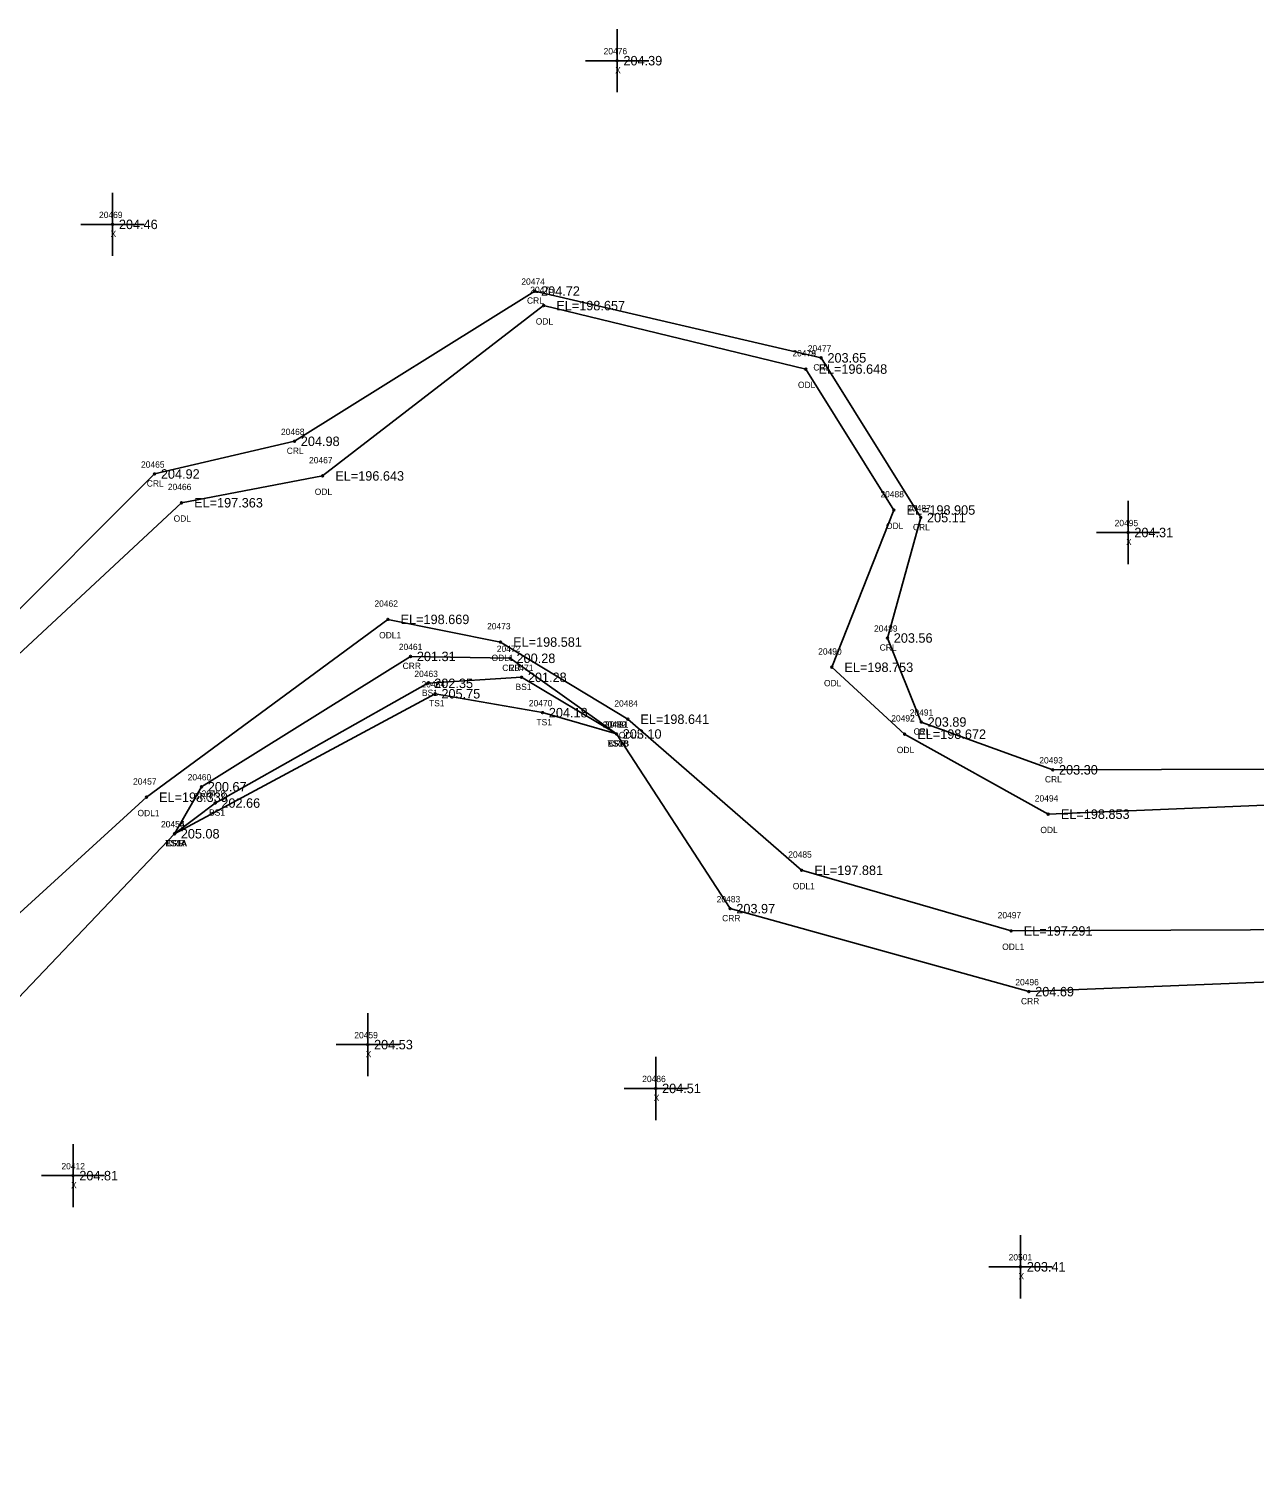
# Model space of a CAD drawing. Extents: x 2260230 to 2261304, y 1064626 to 1065587.
# Drawn here: x 2260916.2 to 2261110.1, y 1065075.6 to 1065305.6 of the extents above; entities that cross this region are included whole.
import ezdxf

# ---------------------------------------------------------------- set-up
doc = ezdxf.new("R2010")
doc.units = 0
for name, color, linetype in [('RD_DTM_BkLn2', 7, 'Continuous'), ('RD_DTM_BkLn_txCode', 7, 'Continuous'), ('RD_EX_H2O', 7, 'Continuous'), ('RD_EX_H2O_txCode', 7, 'Continuous'), ('RD_EX_Misc', 7, 'Continuous'), ('RD_EX_Misc_txCode', 7, 'Continuous'), ('RD_EX_TX_H2O_ELEV', 7, 'Continuous'), ('RD_EX_TX_Misc_ELEV', 7, 'Continuous'), ('RD_SMD_Locator', 7, 'Continuous')]:
    doc.layers.add(name, color=color, linetype=linetype)

msp = doc.modelspace()

# ---------------------------------------------------------------- linework, layer by layer
at = {"layer": 'RD_DTM_BkLn2'}
for points in [[(2260939.15, 1065178.33), (2260945.57, 1065183.19), (2260979.24, 1065202.13), (2260994.05, 1065203.08), (2261009.06, 1065194.12)], [(2260939.15, 1065178.33), (2260980.38, 1065200.48), (2260997.37, 1065197.49), (2261009.06, 1065194.12)]]:
    msp.add_lwpolyline(points, dxfattribs=at)
at = {"layer": 'RD_EX_H2O'}
for points in [[(2260885.41, 1065184.64), (2260936, 1065235.25), (2260958.14, 1065240.42), (2260996.14, 1065264.19), (2261041.44, 1065253.62), (2261057.19, 1065228.35), (2261051.93, 1065209.3), (2261057.29, 1065196.01), (2261078.07, 1065188.45), (2261181.25, 1065188.78), (2261285.07, 1065214.16)], [(2260772.5, 1065076.18), (2260808.2, 1065117.04), (2260848.54, 1065142.46), (2260881.52, 1065170.81), (2260885.55, 1065179.82), (2260940.26, 1065230.7), (2260962.59, 1065234.94), (2260997.55, 1065261.89), (2261039.02, 1065251.85), (2261039.02, 1065251.85), (2261052.94, 1065229.55), (2261043.13, 1065204.67), (2261054.65, 1065194.09), (2261077.36, 1065181.43), (2261181.44, 1065185.78), (2261286.2, 1065209.29)], [(2260798.69, 1065050.24), (2260824.47, 1065095.61), (2260899.49, 1065151.99), (2260934.71, 1065184.11), (2260972.92, 1065212.25), (2260990.72, 1065208.66), (2261010.85, 1065196.45), (2261038.36, 1065172.55), (2261071.49, 1065162.95), (2261185.1, 1065163.45), (2261291.17, 1065187.86)], [(2260835.04, 1065077.78), (2260839.45, 1065081.34), (2260836.25, 1065093.94), (2260905.11, 1065142.54), (2260939.15, 1065178.33), (2260943.42, 1065185.77), (2260976.49, 1065206.39), (2260992.26, 1065206.09), (2261009.06, 1065194.12), (2261027.03, 1065166.48), (2261074.3, 1065153.35), (2261181.18, 1065157.65), (2261291.85, 1065184.94)]]:
    msp.add_lwpolyline(points, dxfattribs=at)
at = {"layer": 'RD_EX_Misc'}
for p, q in [((2261009.17, 1065295.64), (2261009.17, 1065305.64)), ((2261004.17, 1065300.64), (2261014.17, 1065300.64)), ((2260929.36, 1065269.74), (2260929.36, 1065279.74)), ((2260924.36, 1065274.74), (2260934.36, 1065274.74)), ((2261089.99, 1065220.99), (2261089.99, 1065230.99)), ((2261084.99, 1065225.99), (2261094.99, 1065225.99)), ((2260969.72, 1065139.97), (2260969.72, 1065149.97)), ((2260964.72, 1065144.97), (2260974.72, 1065144.97)), ((2261015.28, 1065133.04), (2261015.28, 1065143.04)), ((2261010.28, 1065138.04), (2261020.28, 1065138.04)), ((2260923.1, 1065119.24), (2260923.1, 1065129.24)), ((2260918.1, 1065124.24), (2260928.1, 1065124.24)), ((2261072.97, 1065104.82), (2261072.97, 1065114.82)), ((2261067.97, 1065109.82), (2261077.97, 1065109.82))]:
    msp.add_line(p, q, dxfattribs=at)
at = {"layer": 'RD_SMD_Locator'}
for centre in [(2261009.17, 1065300.64), (2260929.36, 1065274.74), (2260996.14, 1065264.19), (2260997.55, 1065261.89), (2261041.44, 1065253.62), (2261039.02, 1065251.85), (2261039.02, 1065251.85), (2260958.14, 1065240.42), (2260936, 1065235.25), (2260962.59, 1065234.94), (2260940.26, 1065230.7), (2261052.94, 1065229.55), (2261057.19, 1065228.35), (2261089.99, 1065225.99), (2260972.92, 1065212.25), (2260990.72, 1065208.66), (2261051.93, 1065209.3), (2260976.49, 1065206.39), (2260992.26, 1065206.09), (2260994.05, 1065203.08), (2261043.13, 1065204.67), (2260979.24, 1065202.13), (2260980.38, 1065200.48), (2260997.37, 1065197.49), (2261010.85, 1065196.45), (2261057.29, 1065196.01), (2261009.06, 1065194.12), (2261009.06, 1065194.12), (2261009.06, 1065194.12), (2261054.65, 1065194.09), (2261078.07, 1065188.45), (2260934.71, 1065184.11), (2260943.42, 1065185.77), (2260945.57, 1065183.19), (2261077.36, 1065181.43), (2260939.15, 1065178.33), (2260939.15, 1065178.33), (2260939.15, 1065178.33), (2261038.36, 1065172.55), (2261027.03, 1065166.48), (2261071.49, 1065162.95), (2261074.3, 1065153.35), (2260969.72, 1065144.97), (2261015.28, 1065138.04), (2260923.1, 1065124.24), (2261072.97, 1065109.82)]:
    msp.add_circle(centre, 0.15, dxfattribs=at)

# ---------------------------------------------------------------- texts
at = {"layer": 'RD_DTM_BkLn_txCode'}
for s, p in [('20471', (2260992.21, 1065204.08)), ('20463', (2260977.1, 1065203.13)), ('20464', (2260978.23, 1065201.48)), ('BS1', (2260978.3, 1065200.13)), ('BS1', (2260993.1, 1065201.08)), ('TS1', (2260979.42, 1065198.48)), ('20470', (2260995.21, 1065198.49)), ('TS1', (2260996.41, 1065195.49)), ('20480', (2261006.91, 1065195.12)), ('20481', (2261007.23, 1065195.12)), ('TS1B', (2261007.63, 1065192.12)), ('BS1B', (2261007.65, 1065192.12)), ('20458', (2260943.45, 1065184.19)), ('BS1', (2260944.62, 1065181.19)), ('20456', (2260937.01, 1065179.33)), ('20455', (2260937.03, 1065179.33)), ('TS1A', (2260937.7, 1065176.33)), ('BS1A', (2260937.72, 1065176.33))]:
    msp.add_text(s, height=1, dxfattribs=at).set_placement(p)
at = {"layer": 'RD_EX_H2O_txCode'}
for s, p in [('20474', (2260994.02, 1065265.19)), ('20475', (2260995.43, 1065263.89)), ('CRL', (2260994.91, 1065262.19)), ('ODL', (2260996.3, 1065258.89)), ('20477', (2261039.33, 1065254.62)), ('20478', (2261036.9, 1065253.85)), ('20479', (2261036.9, 1065253.85)), ('CRL', (2261040.21, 1065251.62)), ('ODL', (2261037.77, 1065248.85)), ('ODL', (2261037.77, 1065248.85)), ('20468', (2260956, 1065241.42)), ('CRL', (2260956.91, 1065238.42)), ('20465', (2260933.86, 1065236.25)), ('20467', (2260960.44, 1065236.94)), ('CRL', (2260934.77, 1065233.25)), ('20466', (2260938.1, 1065232.7)), ('ODL', (2260961.34, 1065231.94)), ('20488', (2261050.82, 1065231.55)), ('20487', (2261055.07, 1065229.35)), ('ODL', (2260939.02, 1065227.7)), ('ODL', (2261051.7, 1065226.55)), ('CRL', (2261055.96, 1065226.35)), ('20462', (2260970.78, 1065214.25)), ('ODL1', (2260971.52, 1065209.25)), ('20473', (2260988.6, 1065210.66)), ('20489', (2261049.81, 1065210.3)), ('20461', (2260974.64, 1065207.39)), ('20472', (2260990.14, 1065207.09)), ('20490', (2261040.97, 1065206.67)), ('CRL', (2261050.7, 1065207.3)), ('CRR', (2260975.24, 1065204.39)), ('ODL1', (2260989.31, 1065205.66)), ('CRR', (2260991, 1065204.09)), ('ODL', (2261041.89, 1065201.67)), ('20484', (2261008.73, 1065198.45)), ('20491', (2261055.46, 1065197.01)), ('20482', (2261006.95, 1065195.12)), ('20492', (2261052.53, 1065196.09)), ('ODL1', (2261009.44, 1065193.45)), ('CRL', (2261056.06, 1065194.01)), ('CRR', (2261007.81, 1065192.12)), ('ODL', (2261053.41, 1065191.09)), ('20493', (2261075.95, 1065189.45)), ('20457', (2260932.6, 1065186.11)), ('20460', (2260941.24, 1065186.77)), ('CRL', (2261076.84, 1065186.45)), ('CRR', (2260942.17, 1065183.77)), ('20494', (2261075.24, 1065183.43)), ('ODL1', (2260933.3, 1065181.11)), ('20454', (2260937.03, 1065179.33)), ('CRR', (2260937.9, 1065176.33)), ('ODL', (2261076.12, 1065178.43)), ('20485', (2261036.24, 1065174.55)), ('ODL1', (2261036.95, 1065169.55)), ('20483', (2261024.92, 1065167.48)), ('20497', (2261069.37, 1065164.95)), ('CRR', (2261025.78, 1065164.48)), ('ODL1', (2261070.08, 1065159.95)), ('20496', (2261072.16, 1065154.35)), ('CRR', (2261073.05, 1065151.35))]:
    msp.add_text(s, height=1, dxfattribs=at).set_placement(p)
at = {"layer": 'RD_EX_Misc_txCode'}
for s, p in [('20476', (2261007.03, 1065301.64)), ('X', (2261008.86, 1065298.64)), ('20469', (2260927.22, 1065275.74)), ('X', (2260929.04, 1065272.74)), ('20495', (2261087.87, 1065226.99)), ('X', (2261089.67, 1065223.99)), ('20459', (2260967.6, 1065145.97)), ('X', (2260969.4, 1065142.97)), ('20486', (2261013.14, 1065139.04)), ('X', (2261014.96, 1065136.04)), ('20412', (2260921.27, 1065125.24)), ('X', (2260922.79, 1065122.24)), ('20501', (2261071.1, 1065110.82)), ('X', (2261072.66, 1065107.82))]:
    msp.add_text(s, height=1, dxfattribs=at).set_placement(p)
at = {"layer": 'RD_EX_TX_H2O_ELEV'}
for s, p in [('204.72', (2260997.14, 1065263.44)), ('EL=198.657', (2260999.55, 1065261.14)), ('203.65', (2261042.44, 1065252.87)), ('EL=196.648', (2261041.02, 1065251.1)), ('EL=196.648', (2261041.02, 1065251.1)), ('204.98', (2260959.14, 1065239.67)), ('204.92', (2260937, 1065234.5)), ('EL=196.643', (2260964.59, 1065234.19)), ('EL=197.363', (2260942.26, 1065229.95)), ('EL=198.905', (2261054.94, 1065228.8)), ('205.11', (2261058.19, 1065227.6)), ('EL=198.669', (2260974.92, 1065211.5)), ('203.56', (2261052.93, 1065208.55)), ('EL=198.581', (2260992.72, 1065207.91)), ('201.31', (2260977.49, 1065205.64)), ('200.28', (2260993.26, 1065205.34)), ('EL=198.753', (2261045.13, 1065203.92)), ('EL=198.641', (2261012.85, 1065195.7)), ('203.89', (2261058.29, 1065195.26)), ('203.10', (2261010.06, 1065193.37)), ('EL=198.672', (2261056.65, 1065193.34)), ('203.30', (2261079.07, 1065187.7)), ('200.67', (2260944.42, 1065185.02)), ('EL=198.339', (2260936.71, 1065183.36)), ('EL=198.853', (2261079.36, 1065180.68)), ('205.08', (2260940.15, 1065177.58)), ('EL=197.881', (2261040.36, 1065171.8)), ('203.97', (2261028.03, 1065165.73)), ('EL=197.291', (2261073.49, 1065162.2)), ('204.69', (2261075.3, 1065152.6))]:
    msp.add_text(s, height=1.5, dxfattribs=at).set_placement(p)
at = {"layer": 'RD_EX_TX_Misc_ELEV'}
for s, p in [('204.39', (2261010.17, 1065299.89)), ('204.46', (2260930.36, 1065273.99)), ('204.31', (2261090.99, 1065225.24)), ('202.35', (2260980.24, 1065201.38)), ('201.28', (2260995.05, 1065202.33)), ('205.75', (2260981.38, 1065199.73)), ('204.18', (2260998.37, 1065196.74)), ('203.10', (2261010.06, 1065193.37)), ('203.10', (2261010.06, 1065193.37)), ('202.66', (2260946.57, 1065182.44)), ('205.08', (2260940.15, 1065177.58)), ('205.08', (2260940.15, 1065177.58)), ('204.53', (2260970.72, 1065144.22)), ('204.51', (2261016.28, 1065137.29)), ('204.81', (2260924.1, 1065123.49)), ('203.41', (2261073.97, 1065109.07))]:
    msp.add_text(s, height=1.5, dxfattribs=at).set_placement(p)

doc.saveas('drawing.dxf')
